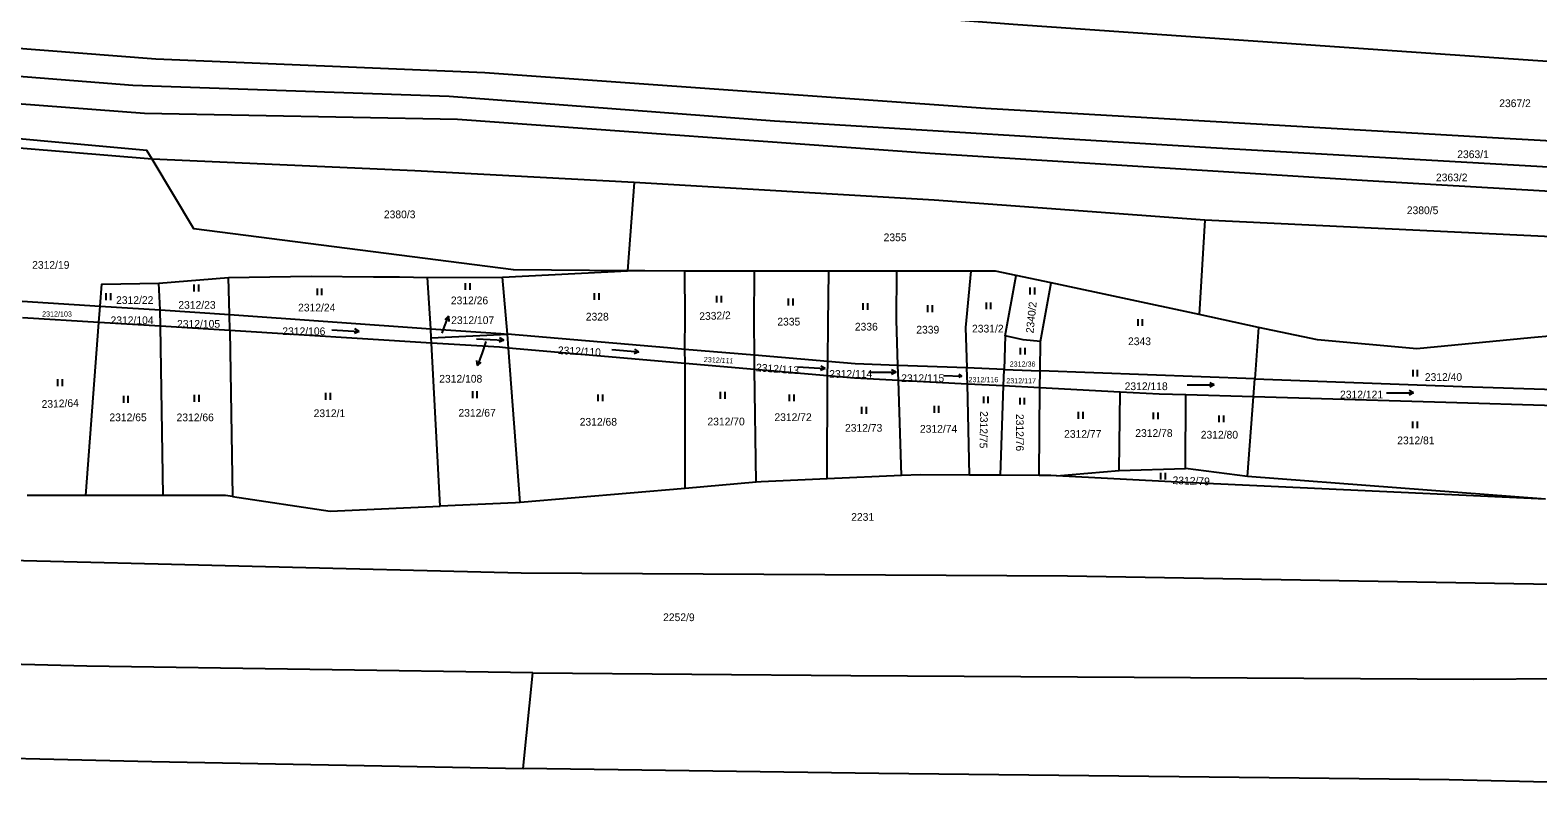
# Model space of a CAD drawing. Extents: x -776734 to -748832, y -1118122 to -976986.
# Drawn here: x -754214.1 to -753881.8, y -1116083.5 to -1115912.8 of the extents above; entities that cross this region are included whole.
import ezdxf

# ---------------------------------------------------------------- set-up
doc = ezdxf.new("R2010")
doc.units = 0
for name, color, linetype in [('KM_Hranice parcel', 7, 'Continuous'), ('KM_Parcelní čísla', 7, 'Continuous'), ('KM_Pop  PČ popisy', 7, 'Continuous'), ('KM_Značky kultur', 7, 'Continuous')]:
    doc.layers.add(name, color=color, linetype=linetype)

msp = doc.modelspace()

# ---------------------------------------------------------------- linework, layer by layer
at = {"layer": 'KM_Hranice parcel'}
for p, q in [((-754080.95, -1115946.36), (-754082.38, -1115965.8)), ((-753955.19, -1115954.63), (-753956.42, -1115975.46)), ((-754185.7, -1115968.5), (-754170.31, -1115967.25)), ((-754170.15, -1115975.45), (-754170.31, -1115967.25)), ((-754126.51, -1115967.24), (-754109.93, -1115967.17)), ((-754125.77, -1115978.56), (-754126.51, -1115967.24)), ((-754109.93, -1115967.17), (-754082.38, -1115965.8)), ((-754108.86, -1115979.77), (-754109.93, -1115967.17)), ((-754054.45, -1115965.84), (-754069.81, -1115965.84)), ((-754038.01, -1115965.85), (-754054.45, -1115965.84)), ((-754023.05, -1115965.86), (-754038.01, -1115965.85)), ((-754006.71, -1115965.87), (-754023.05, -1115965.86)), ((-753999.15, -1115980.16), (-753996.77, -1115966.83)), ((-753989.06, -1115968.48), (-753996.77, -1115966.83)), ((-754185.43, -1115974.39), (-754185.7, -1115968.5)), ((-753991.4, -1115981.38), (-753989.06, -1115968.48)), ((-753956.42, -1115975.46), (-753989.06, -1115968.48)), ((-754215.82, -1115972.47), (-754198.63, -1115973.56)), ((-754198.91, -1115977.17), (-754198.63, -1115973.56)), ((-754198.63, -1115973.56), (-754185.43, -1115974.39)), ((-754185.36, -1115978), (-754185.43, -1115974.39)), ((-754185.43, -1115974.39), (-754170.15, -1115975.45)), ((-754198.91, -1115977.17), (-754215.71, -1115976.14)), ((-754201.78, -1116015.29), (-754198.91, -1115977.17)), ((-754185.36, -1115978), (-754198.91, -1115977.17)), ((-754170.15, -1115975.45), (-754125.77, -1115978.56)), ((-754170.08, -1115978.95), (-754170.15, -1115975.45)), ((-753943.32, -1115978.26), (-753956.42, -1115975.46)), ((-754184.72, -1116015.3), (-754185.36, -1115978)), ((-754170.08, -1115978.95), (-754185.36, -1115978)), ((-754125.6, -1115981.71), (-754170.08, -1115978.95)), ((-754170.08, -1115978.95), (-754169.43, -1116015.54)), ((-754125.67, -1115980.58), (-754125.77, -1115978.56)), ((-754125.67, -1115980.58), (-754108.86, -1115979.77)), ((-754125.6, -1115981.71), (-754125.67, -1115980.58)), ((-754108.63, -1115982.81), (-754108.86, -1115979.77)), ((-753999.15, -1115980.16), (-753999.41, -1115987.51)), ((-753943.32, -1115978.26), (-753944.17, -1115989.6)), ((-754123.68, -1116017.68), (-754125.6, -1115981.71)), ((-754069.72, -1115986.23), (-754108.63, -1115982.81)), ((-754106.04, -1116016.86), (-754108.63, -1115982.81)), ((-754069.72, -1115986.23), (-754069.74, -1115983.12)), ((-754054.45, -1115984.41), (-754069.74, -1115983.12)), ((-754038.28, -1115985.77), (-754054.45, -1115984.41)), ((-754054.4, -1115987.56), (-754054.45, -1115984.41)), ((-753991.47, -1115987.81), (-753991.4, -1115981.38)), ((-754069.71, -1116013.74), (-754069.72, -1115986.23)), ((-754054.4, -1115987.56), (-754069.72, -1115986.23)), ((-754038.32, -1115988.96), (-754054.4, -1115987.56)), ((-754054.05, -1116012.4), (-754054.4, -1115987.56)), ((-754038.32, -1115988.96), (-754038.28, -1115985.77)), ((-754007.61, -1115987.2), (-754022.8, -1115986.63)), ((-754022.69, -1115989.98), (-754022.8, -1115986.63)), ((-753999.41, -1115987.51), (-754007.61, -1115987.2)), ((-754007.5, -1115990.77), (-754007.61, -1115987.2)), ((-753999.54, -1115991.18), (-753999.41, -1115987.51)), ((-753999.41, -1115987.51), (-753991.47, -1115987.81)), ((-753991.51, -1115991.6), (-753991.47, -1115987.81)), ((-753944.17, -1115989.6), (-753991.47, -1115987.81)), ((-754038.4, -1116011.66), (-754038.32, -1115988.96)), ((-754022.05, -1116010.93), (-754022.69, -1115989.98)), ((-754007.5, -1115990.77), (-754022.69, -1115989.98)), ((-754007.01, -1116010.8), (-754007.5, -1115990.77)), ((-753999.54, -1115991.18), (-754007.5, -1115990.77)), ((-754000.23, -1116010.84), (-753999.54, -1115991.18)), ((-753991.51, -1115991.6), (-753999.54, -1115991.18)), ((-753944.46, -1115993.59), (-753944.17, -1115989.6)), ((-753991.67, -1116010.89), (-753991.51, -1115991.6)), ((-753973.83, -1115992.52), (-753991.51, -1115991.6)), ((-753974.04, -1116009.83), (-753973.83, -1115992.52)), ((-753959.44, -1116009.39), (-753959.34, -1115993.15)), ((-753944.46, -1115993.59), (-753959.34, -1115993.15)), ((-753945.75, -1116011.1), (-753944.46, -1115993.59)), ((-754022.05, -1116010.93), (-754038.4, -1116011.66)), ((-754000.23, -1116010.84), (-754007.01, -1116010.8)), ((-753991.67, -1116010.89), (-754000.23, -1116010.84)), ((-753987.84, -1116010.97), (-753974.04, -1116009.83)), ((-753974.04, -1116009.83), (-753959.44, -1116009.39)), ((-753945.75, -1116011.1), (-753959.44, -1116009.39)), ((-753880.11, -1116016.14), (-753945.75, -1116011.1)), ((-754069.71, -1116013.74), (-754106.04, -1116016.86)), ((-754054.05, -1116012.4), (-754069.71, -1116013.74)), ((-754201.78, -1116015.29), (-754214.68, -1116015.29)), ((-754184.72, -1116015.3), (-754201.78, -1116015.29)), ((-753985.44, -1116033.05), (-753874.06, -1116034.91)), ((-754105.4, -1116075.45), (-754103.29, -1116054.43))]:
    msp.add_line(p, q, dxfattribs=at)
for points in [[(-753615.81, -1115947.38), (-753610.67, -1115939.22), (-753713.61, -1115931.92), (-753810.99, -1115924.35), (-753906.45, -1115917.81), (-753997.43, -1115911.53), (-754129.41, -1115901.4), (-754187.71, -1115897.82), (-754213.34, -1115895.19)], [(-753634.31, -1115953.88), (-753782.57, -1115942.57), (-753889.17, -1115936.67), (-754003.5, -1115930.04), (-754113.87, -1115922.18), (-754186.37, -1115919.15), (-754252.67, -1115914.01)], [(-754263.97, -1115919.17), (-754191.45, -1115924.86), (-754121.71, -1115927.28), (-754050.03, -1115932.73), (-753953.82, -1115938.65), (-753852.54, -1115944.45), (-753744.49, -1115950.38), (-753671.97, -1115955.09), (-753644.38, -1115957.57)], [(-754275.03, -1115924.54), (-754188.86, -1115931.02), (-754119.84, -1115932.35), (-754015.78, -1115939.84), (-753919.33, -1115945.89), (-753841.13, -1115950.48), (-753786.6, -1115952.19), (-753712.47, -1115956.3), (-753652.17, -1115960.57)], [(-754187.17, -1115941.21), (-754188.33, -1115939.28), (-754284.42, -1115930.55)], [(-754187.17, -1115941.21), (-754234.35, -1115937.28), (-754261.78, -1115936.04), (-754289.78, -1115933.99)], [(-754080.95, -1115946.36), (-754129.26, -1115943.76), (-754187.17, -1115941.21)], [(-754082.38, -1115965.8), (-754107.54, -1115965.61), (-754178, -1115956.51), (-754187.17, -1115941.21)], [(-753955.19, -1115954.63), (-754014.82, -1115950.25), (-754080.95, -1115946.36)], [(-753701.84, -1115968.54), (-753775.32, -1115961.64), (-753809.26, -1115960.34), (-753852.8, -1115959.54), (-753955.19, -1115954.63)], [(-754170.31, -1115967.25), (-754152.14, -1115966.98), (-754138.37, -1115967.16), (-754132.68, -1115967.16), (-754126.51, -1115967.24)], [(-754069.81, -1115965.84), (-754078.58, -1115965.83), (-754082.38, -1115965.8)], [(-754069.74, -1115983.12), (-754069.73, -1115975.97), (-754069.81, -1115965.84)], [(-754054.45, -1115984.41), (-754054.53, -1115977.05), (-754054.45, -1115965.84)], [(-754038.28, -1115985.77), (-754038.19, -1115977.38), (-754038.01, -1115965.85)], [(-754022.8, -1115986.63), (-754023.13, -1115976.57), (-754023.05, -1115965.86)], [(-754006.71, -1115965.87), (-754007.89, -1115978.31), (-754007.61, -1115987.2)], [(-753996.77, -1115966.83), (-754001.29, -1115965.87), (-754006.71, -1115965.87)], [(-754198.63, -1115973.56), (-754198.26, -1115968.74), (-754185.7, -1115968.5)], [(-754125.77, -1115978.56), (-754110.36, -1115979.64), (-754108.86, -1115979.77)], [(-754069.74, -1115983.12), (-754073.59, -1115982.8), (-754108.86, -1115979.77)], [(-753991.4, -1115981.38), (-753995.24, -1115980.99), (-753999.15, -1115980.16)], [(-753878.37, -1115980.16), (-753883.31, -1115980.58), (-753908.48, -1115983.01), (-753930.35, -1115981.03), (-753943.32, -1115978.26)], [(-754108.63, -1115982.81), (-754110.59, -1115982.64), (-754125.6, -1115981.71)], [(-754022.8, -1115986.63), (-754032.2, -1115986.28), (-754038.28, -1115985.77)], [(-754022.69, -1115989.98), (-754032.41, -1115989.48), (-754038.32, -1115988.96)], [(-753944.17, -1115989.6), (-753898.48, -1115991.32), (-753878.03, -1115991.94)], [(-753959.34, -1115993.15), (-753965.25, -1115992.97), (-753973.83, -1115992.52)], [(-753877.86, -1115995.59), (-753902.09, -1115994.85), (-753944.46, -1115993.59)], [(-754007.01, -1116010.8), (-754017.83, -1116010.74), (-754022.05, -1116010.93)], [(-753987.84, -1116010.97), (-753989.1, -1116010.9), (-753991.67, -1116010.89)], [(-753880.11, -1116016.14), (-753961.19, -1116012.35), (-753987.84, -1116010.97)], [(-754038.4, -1116011.66), (-754052.96, -1116012.31), (-754054.05, -1116012.4)], [(-754169.43, -1116015.54), (-754170.99, -1116015.31), (-754184.72, -1116015.3)], [(-754169.43, -1116015.54), (-754147.92, -1116018.74), (-754123.68, -1116017.68)], [(-754106.04, -1116016.86), (-754107.13, -1116016.95), (-754123.68, -1116017.68)], [(-754224.51, -1116029.41), (-754105.82, -1116032.35), (-753985.44, -1116033.05)], [(-754103.29, -1116054.43), (-754201.58, -1116052.95), (-754353.92, -1116049.07)], [(-754103.29, -1116054.43), (-754033.2, -1116054.99), (-753895.91, -1116055.76), (-753858.39, -1116055.53), (-753761.08, -1116062.05), (-753710.82, -1116068.63), (-753635.35, -1116082.33)], [(-754369.97, -1116067.08), (-754340.19, -1116069.15), (-754298.57, -1116071.31), (-754187.21, -1116073.95), (-754105.4, -1116075.45)], [(-753638.32, -1116101.89), (-753701.48, -1116091.04), (-753750.62, -1116085.3), (-753809.83, -1116082.29), (-753876.57, -1116078.54), (-753901.31, -1116078), (-754026.99, -1116076.59), (-754105.4, -1116075.45)]]:
    msp.add_lwpolyline(points, dxfattribs=at)
at = {"layer": 'KM_Pop  PČ popisy'}
for p, q in [((-754122.94, -1115978.63), (-754121.865, -1115975.828)), ((-754121.865, -1115975.828), (-754122.691, -1115976.584)), ((-754121.865, -1115975.828), (-754121.756, -1115976.943)), ((-754123.28, -1115979.52), (-754122.94, -1115978.63)), ((-754114.47, -1115983.86), (-754115.447, -1115986.697)), ((-754113.6, -1115981.4), (-754114.47, -1115983.86)), ((-754115.447, -1115986.697), (-754115.594, -1115985.588)), ((-754115.447, -1115986.697), (-754114.648, -1115985.914))]:
    msp.add_line(p, q, dxfattribs=at)
at = {"layer": 'KM_Značky kultur'}
for p, q in [((-754197.271, -1115972.25), (-754197.271, -1115970.75)), ((-754196.27, -1115972.25), (-754196.27, -1115970.75)), ((-754177.901, -1115970.35), (-754177.901, -1115968.85)), ((-754176.9, -1115970.35), (-754176.9, -1115968.85)), ((-754150.751, -1115971.19), (-754150.751, -1115969.69)), ((-754149.75, -1115971.19), (-754149.75, -1115969.69)), ((-754118.101, -1115970), (-754118.101, -1115968.5)), ((-754117.1, -1115970), (-754117.1, -1115968.5)), ((-754089.661, -1115972.21), (-754089.661, -1115970.71)), ((-754088.66, -1115972.21), (-754088.66, -1115970.71)), ((-753993.661, -1115970.99), (-753993.661, -1115969.49)), ((-753992.66, -1115970.99), (-753992.66, -1115969.49)), ((-754062.691, -1115972.81), (-754062.691, -1115971.31)), ((-754061.69, -1115972.81), (-754061.69, -1115971.31)), ((-754046.931, -1115973.43), (-754046.931, -1115971.93)), ((-754045.93, -1115973.43), (-754045.93, -1115971.93)), ((-754030.451, -1115974.43), (-754030.451, -1115972.93)), ((-754029.45, -1115974.43), (-754029.45, -1115972.93)), ((-754016.201, -1115974.88), (-754016.201, -1115973.38)), ((-754015.2, -1115974.88), (-754015.2, -1115973.38)), ((-754003.311, -1115974.27), (-754003.311, -1115972.77)), ((-754002.31, -1115974.27), (-754002.31, -1115972.77)), ((-753969.881, -1115977.94), (-753969.881, -1115976.44)), ((-753968.88, -1115977.94), (-753968.88, -1115976.44)), ((-754147.539, -1115978.822), (-754141.547, -1115979.136)), ((-754141.547, -1115979.136), (-754142.549, -1115979.586)), ((-754141.547, -1115979.136), (-754142.497, -1115978.585)), ((-754115.679, -1115980.772), (-754109.687, -1115981.086)), ((-754109.687, -1115981.086), (-754110.689, -1115981.536)), ((-754109.687, -1115981.086), (-754110.637, -1115980.535)), ((-754085.872, -1115983.129), (-754079.895, -1115983.651)), ((-754079.895, -1115983.651), (-754080.912, -1115984.066)), ((-754079.895, -1115983.651), (-754080.825, -1115983.067)), ((-753995.791, -1115984.27), (-753995.791, -1115982.77)), ((-753994.79, -1115984.27), (-753994.79, -1115982.77)), ((-754044.836, -1115986.94), (-754038.851, -1115987.359)), ((-754038.851, -1115987.359), (-754039.861, -1115987.791)), ((-754038.851, -1115987.359), (-754039.791, -1115986.791)), ((-754023.223, -1115988.129), (-754024.2, -1115987.627)), ((-753909.291, -1115989.1), (-753909.291, -1115987.6)), ((-753908.29, -1115989.1), (-753908.29, -1115987.6)), ((-754207.951, -1115991.2), (-754207.951, -1115989.7)), ((-754206.95, -1115991.2), (-754206.95, -1115989.7)), ((-754029.223, -1115988.129), (-754023.223, -1115988.129)), ((-754023.223, -1115988.129), (-754024.2, -1115988.63)), ((-754012.767, -1115988.876), (-754008.75, -1115989.016)), ((-754008.75, -1115989.016), (-754009.416, -1115989.329)), ((-754008.75, -1115989.016), (-754009.393, -1115988.658)), ((-753959.083, -1115990.959), (-753953.083, -1115990.959)), ((-753953.083, -1115990.959), (-753954.06, -1115990.457)), ((-753953.083, -1115990.959), (-753954.06, -1115991.46)), ((-754193.431, -1115994.86), (-754193.431, -1115993.36)), ((-754192.43, -1115994.86), (-754192.43, -1115993.36)), ((-754177.841, -1115994.65), (-754177.841, -1115993.15)), ((-754176.84, -1115994.65), (-754176.84, -1115993.15)), ((-754148.901, -1115994.21), (-754148.901, -1115992.71)), ((-754147.9, -1115994.21), (-754147.9, -1115992.71)), ((-754116.521, -1115993.84), (-754116.521, -1115992.34)), ((-754115.52, -1115993.84), (-754115.52, -1115992.34)), ((-754088.841, -1115994.56), (-754088.841, -1115993.06)), ((-754087.84, -1115994.56), (-754087.84, -1115993.06)), ((-754061.891, -1115993.99), (-754061.891, -1115992.49)), ((-754060.89, -1115993.99), (-754060.89, -1115992.49)), ((-754046.681, -1115994.52), (-754046.681, -1115993.02)), ((-754045.68, -1115994.52), (-754045.68, -1115993.02)), ((-754003.891, -1115994.99), (-754003.891, -1115993.49)), ((-754002.89, -1115994.99), (-754002.89, -1115993.49)), ((-753995.881, -1115995.27), (-753995.881, -1115993.77)), ((-753994.88, -1115995.27), (-753994.88, -1115993.77)), ((-753915.153, -1115992.669), (-753909.153, -1115992.669)), ((-753909.153, -1115992.669), (-753910.13, -1115992.167)), ((-753909.153, -1115992.669), (-753910.13, -1115993.17)), ((-754030.761, -1115997.29), (-754030.761, -1115995.79)), ((-754029.76, -1115997.29), (-754029.76, -1115995.79)), ((-754014.761, -1115997.08), (-754014.761, -1115995.58)), ((-754013.76, -1115997.08), (-754013.76, -1115995.58)), ((-753983.021, -1115998.41), (-753983.021, -1115996.91)), ((-753982.02, -1115998.41), (-753982.02, -1115996.91)), ((-753966.491, -1115998.5), (-753966.491, -1115997)), ((-753965.49, -1115998.5), (-753965.49, -1115997)), ((-753952.011, -1115999.15), (-753952.011, -1115997.65)), ((-753951.01, -1115999.15), (-753951.01, -1115997.65)), ((-753909.321, -1116000.47), (-753909.321, -1115998.97)), ((-753908.32, -1116000.47), (-753908.32, -1115998.97)), ((-753964.861, -1116011.82), (-753964.861, -1116010.32)), ((-753963.86, -1116011.82), (-753963.86, -1116010.32))]:
    msp.add_line(p, q, dxfattribs=at)

# ---------------------------------------------------------------- texts
at = {"layer": 'KM_Parcelní čísla'}
for s, height, p in [('2367/2', 1.7, (-753890.29, -1115929.72)), ('2363/1', 1.7, (-753899.54, -1115940.96)), ('2363/2', 1.7, (-753904.24, -1115946.07)), ('2380/3', 1.7, (-754136.1, -1115954.21)), ('2380/5', 1.7, (-753910.66, -1115953.31)), ('2355', 1.7, (-754025.96, -1115959.27)), ('2312/19', 1.7, (-754213.62, -1115965.35)), ('2312/22', 1.7, (-754195.12, -1115973.1)), ('2312/23', 1.7, (-754181.4, -1115974.16)), ('2312/24', 1.7, (-754155.01, -1115974.75)), ('2312/26', 1.7, (-754121.34, -1115973.17)), ('2312/103', 1.14, (-754211.427, -1115975.88)), ('2312/104', 1.7, (-754196.34, -1115977.55)), ('2312/105', 1.7, (-754181.68, -1115978.34)), ('2312/107', 1.7, (-754121.27, -1115977.53)), ('2328', 1.7, (-754091.6, -1115976.75)), ('2335', 1.7, (-754049.39, -1115977.85)), ('2336', 1.7, (-754032.31, -1115978.96)), ('2339', 1.7, (-754018.76, -1115979.62)), ('2331/2', 1.7, (-754006.48, -1115979.39)), ('2312/106', 1.7, (-754158.48, -1115979.97)), ('2343', 1.7, (-753972.1, -1115982.18)), ('2312/114', 1.7, (-754037.96, -1115989.38)), ('2312/36', 1.14, (-753998.182, -1115986.92)), ('2312/108', 1.7, (-754123.901, -1115990.438)), ('2312/115', 1.7, (-754022.09, -1115990.31)), ('2312/116', 1.14, (-754007.247, -1115990.34)), ('2312/117', 1.14, (-753998.937, -1115990.6)), ('2312/118', 1.7, (-753972.84, -1115992.09)), ('2312/40', 1.7, (-753906.69, -1115990.06)), ('2312/121', 1.7, (-753925.37, -1115993.91)), ('2312/65', 1.7, (-754196.59, -1115998.94)), ('2312/66', 1.7, (-754181.79, -1115998.95)), ('2312/1', 1.7, (-754151.58, -1115998.04)), ('2312/67', 1.7, (-754119.67, -1115997.94)), ('2312/72', 1.7, (-754050.03, -1115998.9)), ('2312/68', 1.7, (-754092.94, -1115999.92)), ('2312/70', 1.7, (-754064.79, -1115999.86)), ('2312/73', 1.7, (-754034.47, -1116001.26)), ('2312/74', 1.7, (-754017.96, -1116001.47)), ('2312/77', 1.7, (-753986.19, -1116002.6)), ('2312/78', 1.7, (-753970.5, -1116002.4)), ('2312/80', 1.7, (-753956.07, -1116002.77)), ('2312/81', 1.7, (-753912.77, -1116004.02)), ('2231', 1.7, (-754033.11, -1116020.89)), ('2252/9', 1.7, (-754074.56, -1116043))]:
    msp.add_text(s, height=height, dxfattribs=at).set_placement(p)
for s, height, rotation, p in [('2340/2', 1.7, 84, (-753992.944, -1115979.618)), ('2332/2', 1.7, 2, (-754066.57, -1115976.669)), ('2312/110', 1.7, 357, (-754097.794, -1115984.128)), ('2312/111', 1.14, 357, (-754065.612, -1115985.885)), ('2312/113', 1.7, 356, (-754054.149, -1115987.927)), ('2312/64', 1.7, 2, (-754211.51, -1115996.029)), ('2312/75', 1.7, 269, (-754004.679, -1115996.695)), ('2312/76', 1.7, 270, (-753996.79, -1115997.34)), ('2312/79', 1.7, 358, (-753962.319, -1116012.789))]:
    msp.add_text(s, height=height, rotation=rotation, dxfattribs=at).set_placement(p)

doc.saveas('drawing.dxf')
